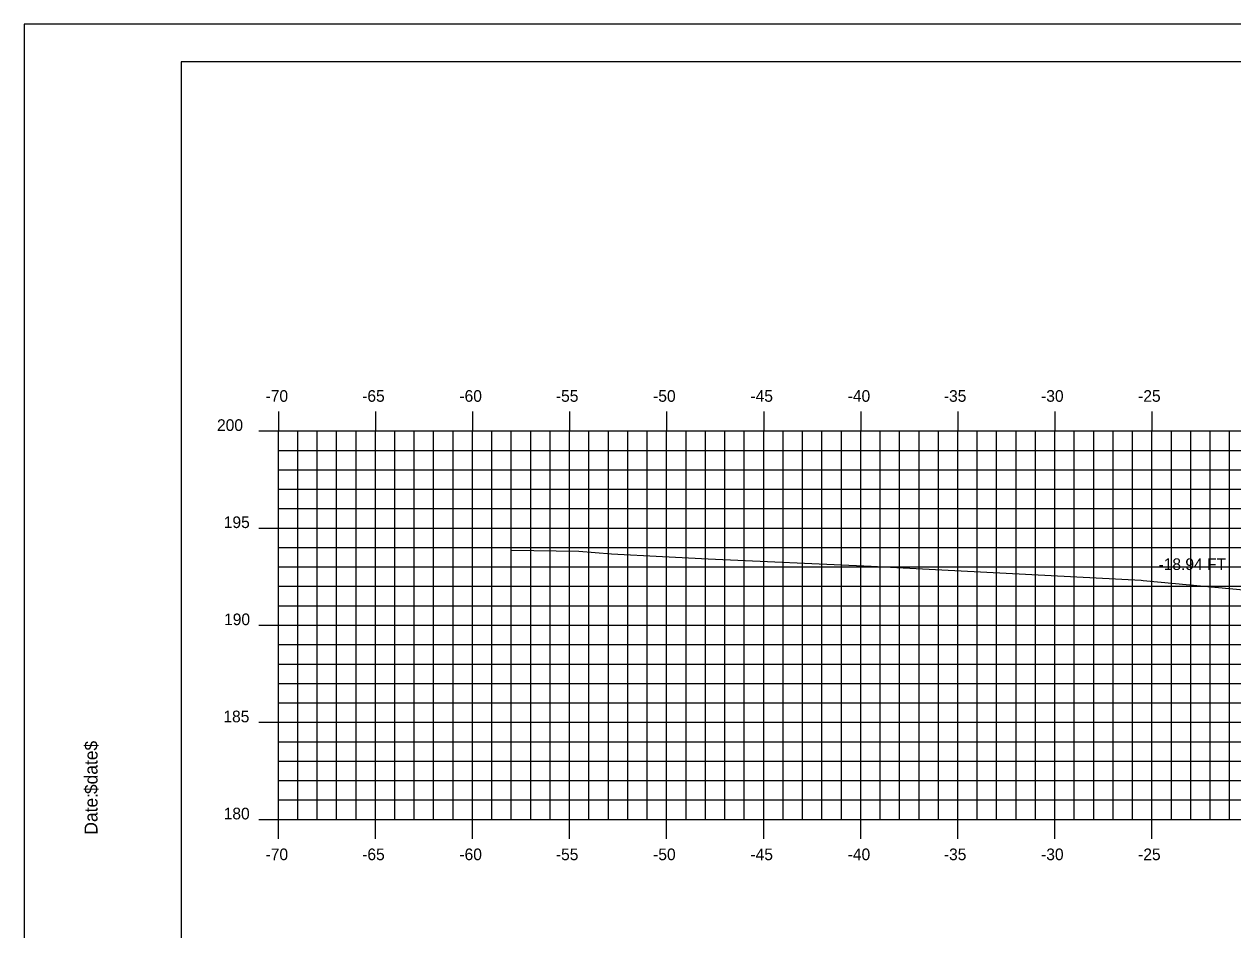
# Model space of a CAD drawing. Extents: x 1139207 to 1139377, y 608981 to 609091.
# Drawn here: x 1139206.6 to 1139268.9, y 609044.6 to 609091.3 of the extents above; entities that cross this region are included whole.
import ezdxf

# ---------------------------------------------------------------- set-up
doc = ezdxf.new("R2010")
doc.units = 0
for name, color, linetype in [('BORDER', 7, 'Continuous'), ('D_Text_Standard', 7, 'Continuous'), ('H_V ANNOTATION', 7, 'Continuous'), ('MAJOR', 7, 'Continuous'), ('MINOR', 7, 'Continuous'), ('PLOT BOUNDARY', 7, 'Continuous'), ('S_Roadway_Centerline', 7, 'Continuous')]:
    doc.layers.add(name, color=color, linetype=linetype)

msp = doc.modelspace()

# ---------------------------------------------------------------- linework, layer by layer
at = {"layer": 'BORDER'}
msp.add_lwpolyline([(1139214.705, 608984.335), (1139374.705, 608984.335), (1139374.705, 609089.335), (1139214.705, 609089.335)], close=True, dxfattribs=at)
at = {"layer": 'MAJOR'}
for p, q in [((1139219.705, 609071.337), (1139219.705, 609070.335)), ((1139224.705, 609071.337), (1139224.705, 609070.335)), ((1139229.705, 609071.337), (1139229.705, 609070.335)), ((1139234.705, 609071.337), (1139234.705, 609070.335)), ((1139239.705, 609071.337), (1139239.705, 609070.335)), ((1139244.705, 609071.337), (1139244.705, 609070.335)), ((1139249.705, 609071.337), (1139249.705, 609070.335)), ((1139254.705, 609071.337), (1139254.705, 609070.335)), ((1139259.705, 609071.337), (1139259.705, 609070.335)), ((1139264.705, 609071.337), (1139264.705, 609070.335)), ((1139218.703, 609070.335), (1139219.705, 609070.335)), ((1139219.705, 609070.335), (1139359.705, 609070.335)), ((1139219.705, 609050.335), (1139219.705, 609070.335)), ((1139219.705, 609050.335), (1139219.705, 609070.335)), ((1139219.705, 609070.335), (1139359.705, 609070.335)), ((1139224.705, 609050.335), (1139224.705, 609070.335)), ((1139229.705, 609050.335), (1139229.705, 609070.335)), ((1139234.705, 609050.335), (1139234.705, 609070.335)), ((1139239.705, 609050.335), (1139239.705, 609070.335)), ((1139244.705, 609050.335), (1139244.705, 609070.335)), ((1139249.705, 609050.335), (1139249.705, 609070.335)), ((1139254.705, 609050.335), (1139254.705, 609070.335)), ((1139259.705, 609050.335), (1139259.705, 609070.335)), ((1139264.705, 609050.335), (1139264.705, 609070.335)), ((1139218.703, 609065.335), (1139219.705, 609065.335)), ((1139219.705, 609065.335), (1139359.705, 609065.335)), ((1139218.703, 609060.335), (1139219.705, 609060.335)), ((1139219.705, 609060.335), (1139359.705, 609060.335)), ((1139218.703, 609055.335), (1139219.705, 609055.335)), ((1139219.705, 609055.335), (1139359.705, 609055.335)), ((1139218.703, 609050.335), (1139219.705, 609050.335)), ((1139219.705, 609050.335), (1139359.705, 609050.335)), ((1139219.705, 609050.335), (1139359.705, 609050.335)), ((1139219.705, 609049.333), (1139219.705, 609050.335)), ((1139224.705, 609049.333), (1139224.705, 609050.335)), ((1139229.705, 609049.333), (1139229.705, 609050.335)), ((1139234.705, 609049.333), (1139234.705, 609050.335)), ((1139239.705, 609049.333), (1139239.705, 609050.335)), ((1139244.705, 609049.333), (1139244.705, 609050.335)), ((1139249.705, 609049.333), (1139249.705, 609050.335)), ((1139254.705, 609049.333), (1139254.705, 609050.335)), ((1139259.705, 609049.333), (1139259.705, 609050.335)), ((1139264.705, 609049.333), (1139264.705, 609050.335))]:
    msp.add_line(p, q, dxfattribs=at)
at = {"layer": 'MINOR'}
for p, q in [((1139220.705, 609050.335), (1139220.705, 609070.335)), ((1139221.705, 609050.335), (1139221.705, 609070.335)), ((1139222.705, 609050.335), (1139222.705, 609070.335)), ((1139223.705, 609050.335), (1139223.705, 609070.335)), ((1139225.705, 609050.335), (1139225.705, 609070.335)), ((1139226.705, 609050.335), (1139226.705, 609070.335)), ((1139227.705, 609050.335), (1139227.705, 609070.335)), ((1139228.705, 609050.335), (1139228.705, 609070.335)), ((1139230.705, 609050.335), (1139230.705, 609070.335)), ((1139231.705, 609050.335), (1139231.705, 609070.335)), ((1139232.705, 609050.335), (1139232.705, 609070.335)), ((1139233.705, 609050.335), (1139233.705, 609070.335)), ((1139235.705, 609050.335), (1139235.705, 609070.335)), ((1139236.705, 609050.335), (1139236.705, 609070.335)), ((1139237.705, 609050.335), (1139237.705, 609070.335)), ((1139238.705, 609050.335), (1139238.705, 609070.335)), ((1139240.705, 609050.335), (1139240.705, 609070.335)), ((1139241.705, 609050.335), (1139241.705, 609070.335)), ((1139242.705, 609050.335), (1139242.705, 609070.335)), ((1139243.705, 609050.335), (1139243.705, 609070.335)), ((1139245.705, 609050.335), (1139245.705, 609070.335)), ((1139246.705, 609050.335), (1139246.705, 609070.335)), ((1139247.705, 609050.335), (1139247.705, 609070.335)), ((1139248.705, 609050.335), (1139248.705, 609070.335)), ((1139250.705, 609050.335), (1139250.705, 609070.335)), ((1139251.705, 609050.335), (1139251.705, 609070.335)), ((1139252.705, 609050.335), (1139252.705, 609070.335)), ((1139253.705, 609050.335), (1139253.705, 609070.335)), ((1139255.705, 609050.335), (1139255.705, 609070.335)), ((1139256.705, 609050.335), (1139256.705, 609070.335)), ((1139257.705, 609050.335), (1139257.705, 609070.335)), ((1139258.705, 609050.335), (1139258.705, 609070.335)), ((1139260.705, 609050.335), (1139260.705, 609070.335)), ((1139261.705, 609050.335), (1139261.705, 609070.335)), ((1139262.705, 609050.335), (1139262.705, 609070.335)), ((1139263.705, 609050.335), (1139263.705, 609070.335)), ((1139265.705, 609050.335), (1139265.705, 609070.335)), ((1139266.705, 609050.335), (1139266.705, 609070.335)), ((1139267.705, 609050.335), (1139267.705, 609070.335)), ((1139268.705, 609050.335), (1139268.705, 609070.335)), ((1139219.705, 609069.335), (1139359.705, 609069.335)), ((1139219.705, 609069.335), (1139220.707, 609069.335)), ((1139219.705, 609068.335), (1139359.705, 609068.335)), ((1139219.705, 609068.335), (1139220.707, 609068.335)), ((1139219.705, 609067.335), (1139359.705, 609067.335)), ((1139219.705, 609067.335), (1139220.707, 609067.335)), ((1139219.705, 609066.335), (1139359.705, 609066.335)), ((1139219.705, 609066.335), (1139220.707, 609066.335)), ((1139219.705, 609064.335), (1139359.705, 609064.335)), ((1139219.705, 609064.335), (1139220.707, 609064.335)), ((1139219.705, 609063.335), (1139359.705, 609063.335)), ((1139219.705, 609063.335), (1139220.707, 609063.335)), ((1139219.705, 609062.335), (1139359.705, 609062.335)), ((1139219.705, 609062.335), (1139220.707, 609062.335)), ((1139219.705, 609061.335), (1139359.705, 609061.335)), ((1139219.705, 609061.335), (1139220.707, 609061.335)), ((1139219.705, 609059.335), (1139359.705, 609059.335)), ((1139219.705, 609059.335), (1139220.707, 609059.335)), ((1139219.705, 609058.335), (1139359.705, 609058.335)), ((1139219.705, 609058.335), (1139220.707, 609058.335)), ((1139219.705, 609057.335), (1139359.705, 609057.335)), ((1139219.705, 609057.335), (1139220.707, 609057.335)), ((1139219.705, 609056.335), (1139359.705, 609056.335)), ((1139219.705, 609056.335), (1139220.707, 609056.335)), ((1139219.705, 609054.335), (1139359.705, 609054.335)), ((1139219.705, 609054.335), (1139220.707, 609054.335)), ((1139219.705, 609053.335), (1139359.705, 609053.335)), ((1139219.705, 609053.335), (1139220.707, 609053.335)), ((1139219.705, 609052.335), (1139359.705, 609052.335)), ((1139219.705, 609052.335), (1139220.707, 609052.335)), ((1139219.705, 609051.335), (1139359.705, 609051.335)), ((1139219.705, 609051.335), (1139220.707, 609051.335))]:
    msp.add_line(p, q, dxfattribs=at)
at = {"layer": 'PLOT BOUNDARY'}
msp.add_lwpolyline([(1139206.612, 608981.276), (1139376.612, 608981.276), (1139376.612, 609091.276), (1139206.612, 609091.276)], close=True, dxfattribs=at)
at = {"layer": 'S_Roadway_Centerline'}
msp.add_lwpolyline([(1139231.693, 609064.2), (1139235.188, 609064.142), (1139236.871, 609064.001), (1139239.489, 609063.871), (1139241.838, 609063.755), (1139250.238, 609063.378), (1139264.143, 609062.648), (1139264.256, 609062.641), (1139272.57, 609061.866), (1139275.873, 609061.633), (1139276.892, 609061.652), (1139282.291, 609061.733), (1139287.04, 609061.756), (1139292.681, 609061.794), (1139292.709, 609061.781), (1139297.486, 609061.69), (1139303.847, 609061.636), (1139305.717, 609061.239), (1139307.637, 609060.852), (1139309.089, 609060.674), (1139312.659, 609060.053), (1139353.311, 609060.081), (1139359.705, 609060.02)], dxfattribs=at)

# ---------------------------------------------------------------- texts
at = {"layer": 'BORDER'}
for s, p in [('$date$', (1139210.39, 609051.64)), ('Date:', (1139210.39, 609049.552))]:
    msp.add_text(s, height=0.6696, rotation=90, dxfattribs=at).set_placement(p)
at = {"layer": 'D_Text_Standard'}
msp.add_text('-18.94 FT', height=0.6, dxfattribs=at).set_placement((1139265.042, 609063.174))
at = {"layer": 'H_V ANNOTATION'}
for s, p in [('-70', (1139219.047, 609071.835)), ('-65', (1139224.023, 609071.835)), ('-60', (1139229.031, 609071.835)), ('-55', (1139234.001, 609071.835)), ('-50', (1139239.009, 609071.835)), ('-45', (1139244.023, 609071.835)), ('-40', (1139249.031, 609071.835)), ('-35', (1139253.985, 609071.835)), ('-30', (1139258.993, 609071.835)), ('-25', (1139263.991, 609071.835)), ('200', (1139216.546, 609070.335)), ('195', (1139216.894, 609065.335)), ('190', (1139216.91, 609060.335)), ('185', (1139216.873, 609055.335)), ('180', (1139216.889, 609050.335)), ('-70', (1139219.047, 609048.235)), ('-65', (1139224.023, 609048.235)), ('-60', (1139229.031, 609048.235)), ('-55', (1139234.001, 609048.235)), ('-50', (1139239.009, 609048.235)), ('-45', (1139244.023, 609048.235)), ('-40', (1139249.031, 609048.235)), ('-35', (1139253.985, 609048.235)), ('-30', (1139258.993, 609048.235)), ('-25', (1139263.991, 609048.235))]:
    msp.add_text(s, height=0.6, dxfattribs=at).set_placement(p)
at = {"layer": 'MAJOR'}
msp.add_text('-', height=0.006, dxfattribs=at).set_placement((1139219.701, 609050.335))

doc.saveas('drawing.dxf')
